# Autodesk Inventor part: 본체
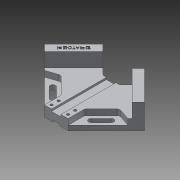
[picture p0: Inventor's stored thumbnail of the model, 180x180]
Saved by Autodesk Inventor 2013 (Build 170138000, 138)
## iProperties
Created: 2019-04
Part Number: 본체
Material: 알루미늄 6061
Document SubType Name: Modeling
Designer: Administrator
Density: 1 g/cm^3
Author: Administrator
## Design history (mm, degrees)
sketch "스케치1"
  geometry: L1 (0, 0)-(0, -20); L2 (0, -169.706)-(35.355, -134.35); L3 (84.853, -84.853)-(20, -20); L4 (35.355, -134.35)-(14.005, -113); L5 (14.005, -113)-(0, -113); L6 (20, -20)-(0, -20); L7 (35.355, -134.35)-(84.853, -84.853); L8 (0, -113)-(0, -169.706); L9 (20, -20)-(0, 0); L10 (0, -20)-(0, -113)
  constraints: 20 end point, 10 perpendicular, 3 vertical, 2 parallel
  dimensions: "d25" = 45 deg angle of L1 L3; "d26" = 120 distance of L2.start L3.start; "d28" = 20 distance of L3.end L1.end; "d29" = 50 distance of L2.start L2.end; "d41" = 93 distance of L1.end L5.end
extrude "돌출1" new body sketch "스케치1" distance "d31" = 18; taper "d32" = 0 deg
sketch "스케치2"
  geometry: L1 (-84.853, 84.853)-(-20, 20) reference; L2 (-14.005, 113)-(-35.355, 134.35) reference; L3 (-35.355, 134.35)-(-84.853, 84.853) reference; L4 (-35.355, 134.35)-(-24.749, 123.744); L5 (-24.749, 123.744)-(-74.246, 74.246); L6 (-84.853, 84.853)-(-35.355, 134.35); L7 (-84.853, 84.853)-(-74.246, 74.246); 1 further point
  constraints: 8 end point, 2 point on line, 1 collinear, 1 perpendicular
  dimensions: "d33" = 15 distance of L2.end L4.end
extrude "돌출2" join sketch "스케치2" distance "d34" = 24; taper "d35" = 0 deg
sketch "스케치3"
  geometry: L1 (-74.246, 74.246)-(-20, 20) reference; L2 (0, 20)-(0, 113) reference; L3 (-35.355, 134.35)-(-84.853, 84.853) reference; L4 (-84.853, 84.853)-(-74.246, 74.246) reference; L5 (-74.246, 74.246)-(-24.749, 123.744) reference; L6 (-24.749, 123.744)-(-35.355, 134.35) reference; L7 (-70.711, 70.711)-(-49.497, 77.782); L8 (-49.497, 77.782)-(-20, 48.284); L9 (-20, 48.284)-(-20, 20); L10 (-70.711, 70.711)-(-20, 20); 1 further point
  constraints: 8 end point, 3 parallel, 1 point on line
  dimensions: "d36" = 20 distance from line of L3 L7.start; "d37" = 20 distance between parallel lines of L8 L10; "d38" = 30 distance from line of L7.end L3
extrude "돌출3" cut sketch "스케치3" distance "d39" = 10; taper "d40" = 0 deg
sketch "스케치4"
  geometry: L1 (-20, 20)-(0, 20) reference; L2 (0, 20)-(0, 113) reference; L3 (0, 20)-(0, 113); L4 (-8, 113)-(-8, 20); L5 (0, 20)-(-8, 20); L6 (0, 113)-(-14.005, 113) reference; L7 (-8, 113)-(0, 113); 1 further point
  constraints: 8 end point, 2 collinear, 2 perpendicular, 1 point on line
  dimensions: "d42" = 8 distance of L4.start L2.end; "d43" = 93 distance of L4.start L4.end (derived)
extrude "돌출4" cut sketch "스케치4" distance "d44" = 3.5; taper "d45" = 0 deg
sketch "스케치6"
  geometry: L1 (0, -20)-(-6, -20); L2 (-6, -20)-(-6, -113); L3 (-6, -113)-(0, -113); L4 (0, -113)-(0, -20); 1 further point
  constraints: 8 end point, 2 parallel, 1 horizontal, 1 perpendicular
  dimensions: "d51" = 6 distance of L3.end L2.end; "d52" = 93 distance of L2.end L1.end
extrude "돌출5" cut sketch "스케치6" distance "d53" = 3; taper "d54" = 0 deg
sketch "스케치7"
  geometry: L1 (-20, -20)-(-6, -20) reference; L2 (0, -20)-(0, -113) reference; 3 further points
  constraints: 1 vertical alignment
  dimensions: "d55" = 6 distance from line of L1 point (-14, -26); "d56" = 12 distance of point (-14, -26) point (-14, -38); "d57" = 14 distance from line of L2 point (-14, -26)
hole "구멍1" sketch "스케치7" at (-14, -26), (-14, -38) diameter "d58" = 4.5; stored, may be unused: countersink angle "d62" = 90 deg, drill point angle "d64" = 118 deg; dims "d59" = 6, "d60" = 8, "d61" = 10, "d63" = 8
fillet "모깎기1" dims "d65" = 5
sketch "스케치8"
  geometry: L1 (-35.355, 134.35)-(-84.853, 84.853) reference; L2 (-24.749, 123.744)-(-35.355, 134.35) reference; 2 further points
  constraints: 1 other
  dimensions: "d66" = 7.5 distance from line of L1 point (-54.801, 104.298); "d67" = 35 distance from line of point (-54.801, 104.298) L2
feature "엠보싱1" sketch "스케치8" dims "d68" = 0.5, "d69" = 0
sketch "스케치9"
  geometry: L1 (-20, 20)-(-70.711, 70.711) reference; L2 (-52.679, 60.458)-(-35.709, 43.487); L3 (-29.345, 49.851)-(-46.315, 66.822); L4 (-35.355, 134.35)-(-84.853, 84.853) reference; L5 (-84.853, 84.853)-(-74.246, 74.246) reference; L6 (-74.246, 74.246)-(-24.749, 123.744) reference; L7 (-24.749, 123.744)-(-35.355, 134.35) reference; L8 (-65.261, 93.526)-(-66.187, 94.452) reference; L9 (-68.154, 92.197)-(-68.451, 92.428) reference; L10 (-66.153, 95.052)-(-63.587, 92.485) reference; L11 (-63.587, 92.485)-(-65.635, 90.437) reference; L12 (-65.635, 90.437)-(-65.899, 90.701) reference; L13 (-65.899, 90.701)-(-64.167, 92.432) reference; L14 (-64.167, 92.432)-(-64.997, 93.262) reference; L15 (-64.997, 93.262)-(-66.542, 91.718) reference; L16 (-66.542, 91.718)-(-66.806, 91.981) reference; L17 (-66.806, 91.981)-(-65.261, 93.526) reference; L18 (-61.687, 93.579)-(-64.781, 96.673) reference; L19 (-64.781, 96.673)-(-64.46, 96.995) reference; L20 (-64.46, 96.995)-(-61.217, 93.752) reference; L21 (-61.217, 93.752)-(-61.471, 93.497) reference; L22 (-60.939, 94.471)-(-63.784, 97.316) reference; L23 (-63.784, 97.316)-(-63.462, 97.637) reference; L24 (-63.462, 97.637)-(-61.75, 95.925) reference; L25 (-61.75, 95.925)-(-61.02, 96.654) reference; L26 (-61.02, 96.654)-(-60.776, 96.409) reference; L27 (-60.776, 96.409)-(-61.505, 95.68) reference; L28 (-61.505, 95.68)-(-60.449, 94.625) reference; L29 (-60.449, 94.625)-(-60.713, 94.361) reference; L30 (-65.563, 97.254)-(-65.827, 97.517) reference; L31 (-65.827, 97.517)-(-62.771, 100.573) reference; L32 (-62.771, 100.573)-(-61.419, 99.22) reference; L33 (-61.419, 99.22)-(-61.654, 98.985) reference; L34 (-61.879, 99.048)-(-62.824, 99.993) reference; L35 (-62.824, 99.993)-(-65.563, 97.254) reference; L36 (-62.34, 97.11)-(-62.368, 97.57) reference; L37 (-60.608, 99.619)-(-60.147, 99.599) reference; L38 (-59.053, 96.289)-(-59.337, 96.006) reference; L39 (-59.759, 100.727)-(-60.075, 100.41) reference; L40 (-58.698, 99.091)-(-58.377, 99.412) reference; L41 (-54.194, 101.533)-(-54.487, 101.825) reference; L42 (-54.487, 101.825)-(-53.383, 102.929) reference; L43 (-53.383, 102.929)-(-56.626, 106.172) reference; L44 (-56.626, 106.172)-(-56.305, 106.493) reference; L45 (-56.305, 106.493)-(-53.062, 103.25) reference; L46 (-53.062, 103.25)-(-51.963, 104.349) reference; L47 (-51.963, 104.349)-(-51.671, 104.056) reference; L48 (-51.671, 104.056)-(-54.194, 101.533) reference; L49 (-48.265, 112.039)-(-49.545, 110.758) reference; L50 (-49.545, 110.758)-(-51.047, 112.259) reference; L51 (-51.047, 112.259)-(-50.721, 112.585) reference; L52 (-50.721, 112.585)-(-49.483, 111.348) reference; L53 (-49.483, 111.348)-(-46.773, 114.058) reference; L54 (-46.773, 114.058)-(-46.509, 113.794) reference; L55 (-46.509, 113.794)-(-47.943, 112.36) reference; L56 (-47.943, 112.36)-(-47.08, 111.496) reference; L57 (-47.08, 111.496)-(-45.127, 113.449) reference; L58 (-45.127, 113.449)-(-44.863, 113.185) reference; L59 (-44.863, 113.185)-(-47.953, 110.096) reference; L60 (-46.974, 108.714)-(-44.283, 111.405) reference; L61 (-44.283, 111.405)-(-44.014, 111.137) reference; L62 (-44.014, 111.137)-(-47.046, 108.105) reference; L63 (-48.303, 109.745)-(-49.109, 108.94) reference; L64 (-49.109, 108.94)-(-49.373, 109.203) reference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; A1 r 4.5 centre (-32.527, 46.669) between (-35.709, 43.487) and (-29.345, 49.851); A2 r 4.5 centre (-49.497, 63.64) between (-46.315, 66.822) and (-52.679, 60.458); 54 further points
  constraints: 4 end point, 4 point on circle, 4 tangent, 2 centre point, 2 parallel, 1 horizontal alignment, 67 other
  dimensions: "d70" = 40 distance from line of L4 A2.centre; "d71" = 24 distance of L2.start L2.end; "d72" = 9 distance between parallel lines of L2 L3; "d73" = 10 distance from line of L5 A2.centre
extrude "돌출6" cut sketch "스케치9" stored distance "d74" = 3; taper "d75" = 0 deg
node "솔리드1"
mirror "대칭1"
mirror "대칭2"
node "투영된 루프1"
node "투영된 루프3"
